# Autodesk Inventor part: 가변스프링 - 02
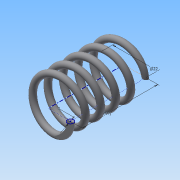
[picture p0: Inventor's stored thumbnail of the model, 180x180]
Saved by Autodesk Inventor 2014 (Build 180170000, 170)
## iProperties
Created: 2015-09
Part Number: 가변스프링 - 02
Material: 강철, 탄소
Document SubType Name: Modeling
Designer: study
Density: 1 g/cm^3
Appearance: 반연마
Mass: 2.38958 g
Surface Area: 32.4556 cm^2
Volume: 2.38958 cm^3
Author: study
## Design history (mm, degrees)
sketch "스케치1"
  geometry: L1 (0, 0)-(11, 0); L2 (11, 0)-(11, 29.193); L3 (11, 29.193)-(0, 29.193); L4 (0, 29.193)-(0, 0); C1 r 1.5 at (11, 0)
  constraints: 8 end point, 2 parallel, 1 centre point, 1 coincident, 1 horizontal, 1 perpendicular
  dimensions: "d0" = 22 diameter of L2 L4; "d1" = 29.19259 distance of L1.end L2.end (derived); "d2" = 3 diameter of C1
feature "코일1" sketch "스케치1" pitch "d3" = 10; turns "d5" = 5; dims "d4" = 29.19259 (= d1), "d6" = 0, angle "d7" = 90 deg, angle "d8" = 90 deg, "d9" = 0, "d10" = 0
node "작업 평면1"
sketch "스케치2"
  geometry: L1 (-12.5, 0)-(-9.5, 0) reference; 1 further point
  constraints: 1 horizontal alignment
extrude "돌출1" cut sketch "스케치2" stored distance "d12" = 10; taper "d13" = 0 deg
node "작업 평면2"
sketch "스케치3"
  geometry: L1 (-9.5, 0)-(-12.5, 0) reference; 1 further point
  constraints: 1 horizontal alignment
extrude "돌출2" cut sketch "스케치3" stored distance "d15" = 10; taper "d16" = 0 deg
node "솔리드1"
node "절단 모서리 투영1"
node "절단 모서리 투영2"
other parameters: "d11" = 0, "d14" = 29.19259 (= d1)
